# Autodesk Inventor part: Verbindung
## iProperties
Created: 2003-12
Part Number: Verbindung
Material: Aluminium - 6061
Document SubType Name: Modellieren
Designer: Ulrich
Control State: 0
Master: False
Checked Out: False
Shininess: 20.0
Angle Display Precision: 2
Document Length Units: 11269
Document Angle Units: 11279
Document Time Units: 11290
Document Mass Units: 11283
Document Length Units Precision: 3
Document Angle Units Precision: 2
Density: 0.0
Volumn: 0.0
Area: 0.0
PropertySet Name: Model Information
Author: Ulrich
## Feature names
1. Grundkörper [Extrusion]
2. VK_Führung [Hole]
3. VK_Befestigung [Hole]
4. Luftkanal_quer [Hole]
5. Luftkanal-Ak [Hole]
6. AK_Befestigung [Hole]
7. Bohrung7 [Hole]
